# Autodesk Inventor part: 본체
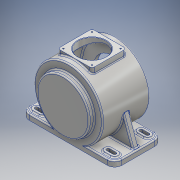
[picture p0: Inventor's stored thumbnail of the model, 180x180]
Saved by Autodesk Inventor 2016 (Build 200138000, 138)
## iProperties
Created: 2015-06
Part Number: 본체
Material: 알루미늄 6061
Document SubType Name: Modeling
Designer: Administrator
Density: 2.7 g/cm^3
Appearance: 알루미늄 - 평지
Mass: 3248.07 g
Surface Area: 2328.34 cm^2
Volume: 1202.99 cm^3
Author: Administrator
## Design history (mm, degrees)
sketch "스케치1"
  geometry: C1 r 85 at (0, 0); 1 further point
  constraints: 1 centre point, 1 coincident
  dimensions: "d0" = 170 diameter of C1
extrude "돌출1" new body sketch "스케치1" stored distance "d1" = 118; taper "d2" = 0 deg
sketch "스케치2"
  geometry: C1 r 65 at (0, 0); 1 further point
  constraints: 1 centre point, 1 coincident
  dimensions: "d3" = 130 diameter of C1
extrude "돌출2" join sketch "스케치2" distance "d4" = 62; taper "d6" = 0 deg; dims "d5" = 72, "d7" = 0
node "작업 평면1"
sketch "스케치3"
  geometry: L1 (-42.5, 42.5)-(42.5, 42.5); L2 (42.5, 42.5)-(42.5, -42.5); L3 (42.5, -42.5)-(-42.5, -42.5); L4 (-42.5, -42.5)-(-42.5, 42.5); 3 further points
  constraints: 8 end point, 2 midpoint, 2 parallel, 2 perpendicular, 1 horizontal, 1 horizontal alignment, 1 vertical alignment
  dimensions: "d9" = 85 distance of L1.start L1.end
extrude "돌출3" join sketch "스케치3" stored distance "d10" = 72; taper "d11" = 0 deg
fillet "모깎기1" dims "d31" = 7
sketch "스케치7"
  geometry: A1 r 7 centre (-35.5, 35.5) between (-35.5, 42.5) and (-42.5, 35.5) reference; A2 r 7 centre (-35.5, -35.5) between (-42.5, -35.5) and (-35.5, -42.5) reference; A3 r 7 centre (35.5, -35.5) between (35.5, -42.5) and (42.5, -35.5) reference; A4 r 7 centre (35.5, 35.5) between (42.5, 35.5) and (35.5, 42.5) reference; 5 further points
  constraints: 4 coincident
hole "구멍2" sketch "스케치7" at (-35.5, -35.5), (35.5, -35.5), (35.5, 35.5), (-35.5, 35.5) diameter "d41" = 3.242; stored, may be unused: countersink angle "d45" = 90 deg, drill point angle "d47" = 118 deg; dims "d42" = 10, "d43" = 4, "d44" = 2, "d46" = 13
node "작업 평면2"
sketch "스케치9"
  geometry: L1 (115, -59)-(-115, -59); L2 (-115, -59)-(-115, 59); L3 (-115, 59)-(115, 59); L4 (115, 59)-(115, -59); 3 further points
  constraints: 8 end point, 2 midpoint, 2 parallel, 1 horizontal, 1 horizontal alignment, 1 perpendicular, 1 vertical alignment
  dimensions: "d57" = 118 distance between parallel lines of L3 L1; "d58" = 230 distance between parallel lines of L2 L4
extrude "돌출4" join sketch "스케치9" distance "d59" = 14; taper "d60" = 0 deg
fillet "모깎기2" dims "d61" = 18
sketch "스케치10"
  geometry: L1 (-97, 59)-(97, 59) reference; L2 (0, 59)-(0, -59); L3 (97, -59)-(-97, -59) reference; L4 (81, 50)-(97, 50); L5 (97, 32)-(81, 32); A1 r 9 centre (97, 41) between (97, 32) and (97, 50); A2 r 9 centre (81, 41) between (81, 50) and (81, 32); 1 further point
  constraints: 6 end point, 4 point on circle, 2 centre point, 2 midpoint, 2 vertical alignment, 1 equal radius, 1 horizontal, 1 parallel
  dimensions: "d62" = 18 distance between parallel lines of L5 L4; "d63" = 16 distance of A1.centre A2.centre; "d64" = 9 radius of A1; "d65" = 18 distance from line of A1.centre L1; "d66" = 97 distance from line of L2 A1.centre
extrude "돌출5" join sketch "스케치10" distance "d68" = 3; taper "d69" = 0 deg
sketch "스케치11"
  geometry: L1 (97, 32)-(81, 32) reference; L2 (81, 50)-(97, 50) reference; L3 (51, -59)-(-51, -59) reference; L4 (-51, -59)-(-51, 59) reference; L5 (-51, 59)-(51, 59) reference; L6 (51, 59)-(51, -59) reference; L7 (81, 37)-(97, 37); L8 (81, 45)-(97, 45); A1 r 9 centre (97, 41) between (97, 32) and (97, 50) reference; A2 r 9 centre (81, 41) between (81, 50) and (81, 32) reference; A3 r 4 centre (81, 41) between (81, 45) and (81, 37); A4 r 4 centre (97, 41) between (97, 37) and (97, 45); 1 further point
  constraints: 4 end point, 4 point on circle, 2 centre point, 2 coincident, 2 horizontal, 2 tangent
  dimensions: "d70" = 8 diameter of A3; "d71" = 8 diameter of A4
extrude "돌출6" cut sketch "스케치11" stored distance "d72" = 0; taper "d73" = 0 deg
sketch "스케치12"
  geometry: L1 (84.87, -4.703)-(109, -71); L2 (-84.87, -4.703)-(-109, -71); L3 (-115, -71)-(-97, -71) reference; L4 (97, -71)-(115, -71) reference; L5 (115, -85)-(115, -71) reference; L6 (-115, -71)-(-115, -85) reference; L7 (46.733, -71)-(97, -71) reference; L8 (-97, -71)-(-46.733, -71) reference; A1 r 85 centre (0, 0) between (46.733, -71) and (-46.733, -71) reference; 1 further point
  constraints: 4 end point, 2 point on circle, 2 point on line
  dimensions: "d80" = 6 distance from line of L1.end L5; "d81" = 110 deg angle of L1 L4; "d82" = 6 distance from line of L6 L2.end; "d83" = 110 deg angle of L3 L2
feature "리브1" sketch "스케치12" dims "d84" = 1, "d85" = 15, "d86" = 0, "d87" = 0, "d88" = 1, "d89" = 1
sketch "스케치13"
  geometry: L1 (0, 0)-(77.036, 35.923); L2 (0, 0)-(85, 0); A1 r 85 centre (0, 0) between (46.733, -71) and (-46.733, -71) reference; 1 further point
  constraints: 4 end point, 2 point on circle, 1 horizontal
  dimensions: "d90" = 25 deg angle of L2 L1
node "작업 평면3"
sketch "스케치14"
  geometry: 2 further points
  constraints: 1 coincident, 1 other
feature "엠보싱1" sketch "스케치14" dims "d91" = 0.5, "d92" = 0
fillet "모깎기3" dims "d93" = 3
sketch "스케치16"
  geometry: L1 (-72, -62)-(-72, 62) reference; L2 (62, -65)-(62, 65) reference; L3 (-72, 0)-(62, 0); L4 (-64.5, 0)-(-64.5, 12); L5 (-62, -65)-(-62, 65) reference; L6 (-61.5, 15)-(-61.5, 15); L7 (-61.5, 15)-(-61.5, 23.2); L8 (-61.2, 23.5)-(-48.5, 23.5); L9 (-47.5, 24.5)-(-47.5, 29.368); L10 (-47.5, 29.368)-(-49.268, 30.192); L11 (-51, 32.911)-(-51, 74); L12 (-48, 77)-(48, 77); L13 (35.5, 72.756)-(-35.5, 72.756) reference; L14 (51, 74)-(51, 47.5); L15 (51, 47.5)-(62, 47.5); L16 (59, 82)-(59, -74) reference; L17 (-48.5, 23.5)-(-47.5, 24.5); A1 r 0.3 centre (-61.2, 23.2) between (-61.2, 23.5) and (-61.5, 23.2); A2 r 3 centre (-61.5, 12) between (-61.5, 15) and (-64.5, 12); A3 r 3 centre (-48, 32.911) between (-51, 32.911) and (-49.268, 30.192); A4 r 3 centre (-48, 74) between (-48, 77) and (-51, 74); A5 r 3 centre (48, 74) between (51, 74) and (48, 77); 3 further points
  constraints: 24 end point, 10 point on circle, 10 tangent, 6 point on line, 5 centre point, 5 perpendicular, 3 parallel, 2 midpoint, 1 equal radius, 1 vertical
  dimensions: "d97" = 30 diameter of L6 L3; "d98" = 3 distance between parallel lines of L7 L4; "d99" = 14 distance between parallel lines of L9 L7; "d100" = 115 deg angle of L10 L11; "d101" = 154 diameter of L12 L3; "d104" = 102 distance between parallel lines of L14 L11; "d105" = 95 diameter of L15 L3; "d106" = 8 distance between parallel lines of L16 L14; "d107" = 62 diameter of point (-51, 31) L3; "d108" = 47 diameter of L8 L3; "d109" = 3.5 distance between parallel lines of L9 L11; "d110" = 0.3 radius of A1; "d111" = 3 radius of A2; "d112" = 1 distance of L8.end point (-47.5, 23.5); "d113" = 1 distance of L9.start point (-47.5, 23.5) (= d112); "d114" = 3 radius of A3; "d115" = 3 radius of A5
revolve "회전2" sketch "스케치16" stored, may be unused: angle "d116" = 90 deg
sketch "스케치18"
  geometry: 2 further points
  constraints: 1 coincident
hole "구멍5" sketch "스케치18" at (0, 0) diameter "d125" = 70; stored, may be unused: countersink angle "d129" = 90 deg, drill point angle "d131" = 0 deg; dims "d126" = 8, "d127" = 4, "d128" = 2, "d130" = 50
sketch "스케치17"
  geometry: A1 r 55 centre (0, 0) between (0, -55) and (55, 0); 3 further points
  constraints: 4 point on circle, 2 horizontal alignment, 2 vertical alignment, 1 centre point, 1 coincident
  dimensions: "d117" = 110 diameter of A1
hole "구멍4" sketch "스케치17" at (0, -55), (55, 0), (0, 55), (-55, 0) diameter "d118" = 3.242; stored, may be unused: countersink angle "d122" = 90 deg, drill point angle "d124" = 118 deg; dims "d119" = 8, "d120" = 4, "d121" = 2, "d123" = 50
chamfer "모따기2" distance "d132" = 1; stored, may be unused: second distance "d133" = 2, angle "d134" = 45 deg
fillet "모깎기4" dims "d135" = 3
fillet "모깎기5" dims "d136" = 3
node "솔리드1"
pattern_linear "직사각형 패턴1" dims "d76" = 82, "d79" = 178
mirror "대칭1"
node "절단 모서리 투영1"
other parameters: "d8" = 88, "d56" = -85
